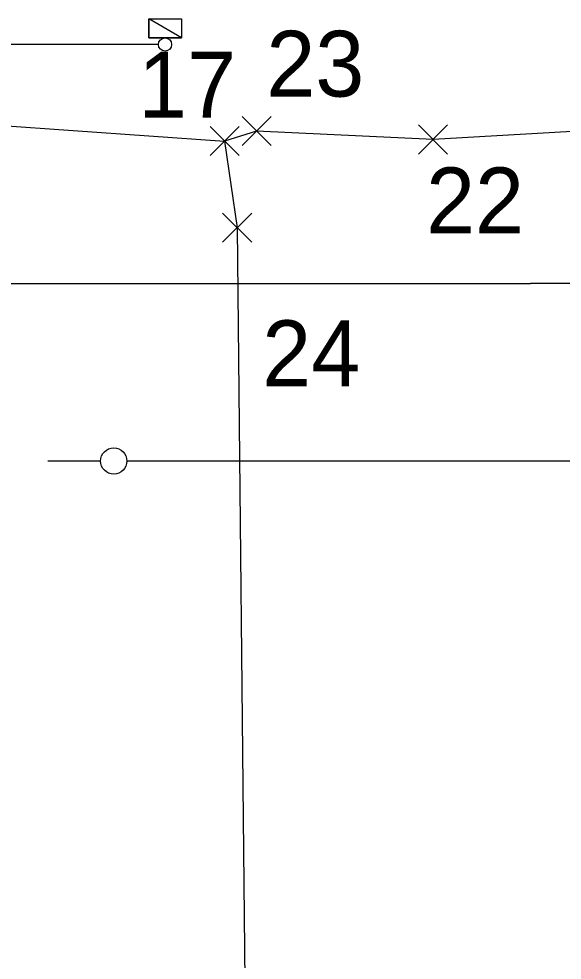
# Model space of a CAD drawing. Extents: x -263993 to -263783, y -1242294 to -1242146.
# Drawn here: x -263923.07 to -263914.81, y -1242207.77 to -1242193.46 of the extents above; entities that cross this region are included whole.
import ezdxf

# ---------------------------------------------------------------- set-up
doc = ezdxf.new("R2010")
doc.units = 0
for name, color, linetype in [('KFA_2D_SITUACIA_DSP', 7, 'Continuous'), ('KFA_ROZVODY_NN_BODY', 7, 'Continuous'), ('KFA_ROZVODY_NN_TRASA', 7, 'Continuous')]:
    doc.layers.add(name, color=color, linetype=linetype)

msp = doc.modelspace()

# ---------------------------------------------------------------- linework, layer by layer
at = {"layer": 'KFA_2D_SITUACIA_DSP'}
for p, q in [((-263921.093, -1242193.752), (-263921.093, -1242193.462)), ((-263921.093, -1242193.462), (-263920.593, -1242193.462)), ((-263920.593, -1242193.752), (-263921.093, -1242193.462)), ((-263920.593, -1242193.752), (-263921.093, -1242193.462)), ((-263921.093, -1242193.462), (-263921.093, -1242193.752)), ((-263920.593, -1242193.462), (-263920.593, -1242193.752)), ((-263920.593, -1242193.752), (-263921.093, -1242193.752)), ((-263921.093, -1242193.752), (-263920.593, -1242193.752)), ((-263920.944, -1242193.852), (-263925.798, -1242193.852)), ((-263923.393, -1242197.482), (-263915.293, -1242197.482)), ((-263914.293, -1242197.482), (-263915.293, -1242197.482)), ((-263921.824, -1242200.182), (-263922.624, -1242200.182)), ((-263915.293, -1242200.182), (-263921.424, -1242200.182)), ((-263909.043, -1242200.182), (-263915.293, -1242200.182))]:
    msp.add_line(p, q, dxfattribs=at)
for centre, radius in [((-263920.844, -1242193.852), 0.1), ((-263921.624, -1242200.182), 0.2)]:
    msp.add_circle(centre, radius, dxfattribs=at)
at = {"layer": 'KFA_ROZVODY_NN_BODY'}
for p, q in [((-263919.674, -1242195.388), (-263919.232, -1242194.946)), ((-263919.232, -1242195.388), (-263919.674, -1242194.946)), ((-263920.16, -1242195.54), (-263919.718, -1242195.098)), ((-263919.718, -1242195.54), (-263920.16, -1242195.098)), ((-263916.993, -1242195.517), (-263916.551, -1242195.075)), ((-263916.551, -1242195.517), (-263916.993, -1242195.075)), ((-263919.97, -1242196.858), (-263919.528, -1242196.416)), ((-263919.528, -1242196.858), (-263919.97, -1242196.416))]:
    msp.add_line(p, q, dxfattribs=at)
at = {"layer": 'KFA_ROZVODY_NN_TRASA'}
for p, q in [((-263924.776, -1242194.984), (-263919.939, -1242195.319)), ((-263919.453, -1242195.167), (-263919.939, -1242195.319)), ((-263916.772, -1242195.296), (-263919.453, -1242195.167)), ((-263914.168, -1242195.145), (-263916.772, -1242195.296)), ((-263919.939, -1242195.319), (-263919.749, -1242196.637)), ((-263919.749, -1242196.637), (-263919.32, -1242238.606))]:
    msp.add_line(p, q, dxfattribs=at)

# ---------------------------------------------------------------- texts
at = {"layer": 'KFA_ROZVODY_NN_BODY'}
for s, p in [('23', (-263919.305, -1242194.644)), ('17', (-263921.253, -1242194.962)), ('22', (-263916.878, -1242196.722)), ('24', (-263919.368, -1242199.045))]:
    msp.add_text(s, height=1, dxfattribs=at).set_placement(p)

doc.saveas('drawing.dxf')
